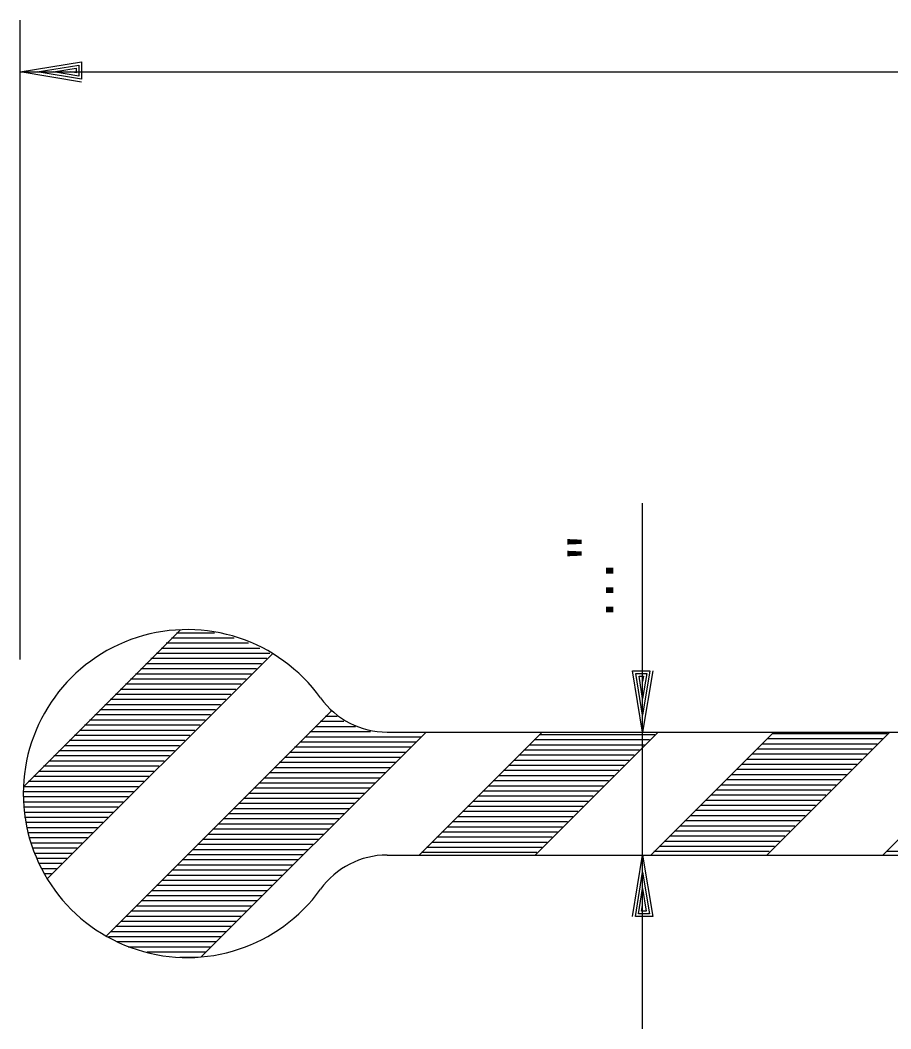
# Model space of a CAD drawing. Extents: x 44743.44 to 44747.1, y 44738.46 to 44741.29.
# Drawn here: x 44744.0225 to 44744.2437, y 44738.8171 to 44739.0734 of the extents above; entities that cross this region are included whole.
import ezdxf

# ---------------------------------------------------------------- set-up
doc = ezdxf.new("R2010")
doc.units = 0
for name, color, linetype in [('Level 1', 7, 'Continuous'), ('Level 10', 7, 'Continuous'), ('Level 8', 7, 'Continuous'), ('S-ANNO-TEXT', 7, 'Continuous')]:
    doc.layers.add(name, color=color, linetype=linetype)

msp = doc.modelspace()

# ---------------------------------------------------------------- linework, layer by layer
at = {"layer": 'Level 1'}
for p, q in [((44744.022493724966, 44738.91099515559), (44744.022493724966, 44739.07343265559)), ((44744.022493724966, 44739.060286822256), (44744.77199372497, 44739.060286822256)), ((44744.022493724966, 44739.060286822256), (44744.022493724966, 44739.060286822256)), ((44744.026827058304, 44739.060286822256), (44744.026827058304, 44739.060286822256)), ((44744.180629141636, 44738.89252640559), (44744.180629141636, 44738.95066182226)), ((44744.180629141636, 44738.896859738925), (44744.180629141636, 44738.896859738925)), ((44744.180629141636, 44738.86127640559), (44744.180629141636, 44738.89252640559)), ((44744.180629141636, 44738.89252640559), (44744.180629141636, 44738.89252640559)), ((44744.180629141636, 44738.81712015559), (44744.180629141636, 44738.86127640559)), ((44744.180629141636, 44738.86127640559), (44744.180629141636, 44738.86127640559)), ((44744.180629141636, 44738.85694307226), (44744.180629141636, 44738.85694307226))]:
    msp.add_line(p, q, dxfattribs=at)
for points in [[(44744.0380770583, 44739.05770348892), (44744.022493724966, 44739.060286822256), (44744.0380770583, 44739.06287015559), (44744.0380770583, 44739.05845348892), (44744.026827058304, 44739.060286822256), (44744.03741039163, 44739.06203682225), (44744.03741039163, 44739.05920348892), (44744.03099372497, 44739.060286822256), (44744.036743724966, 44739.06120348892), (44744.036743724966, 44739.06003682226), (44744.0353270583, 44739.060286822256)], [(44744.0622020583, 44738.917786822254), (44744.07187914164, 44738.917786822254)], [(44744.18321247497, 44738.90810973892), (44744.180629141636, 44738.89252640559), (44744.1780458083, 44738.90810973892), (44744.182462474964, 44738.90810973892), (44744.180629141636, 44738.896859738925), (44744.17887914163, 44738.907443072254), (44744.181712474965, 44738.907443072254), (44744.180629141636, 44738.90102640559), (44744.179712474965, 44738.90677640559), (44744.18087914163, 44738.90677640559), (44744.180629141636, 44738.90535973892)], [(44744.10130622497, 44738.89787015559), (44744.10144164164, 44738.89787015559)], [(44744.15437914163, 44738.89192223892), (44744.183712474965, 44738.89192223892)], [(44744.21366039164, 44738.89218265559), (44744.2428583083, 44738.89218265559)], [(44744.1780458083, 44738.84569307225), (44744.180629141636, 44738.86127640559), (44744.18321247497, 44738.84569307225), (44744.1787958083, 44738.84569307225), (44744.180629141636, 44738.85694307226), (44744.18237914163, 44738.84635973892), (44744.1795458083, 44738.84635973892), (44744.180629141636, 44738.85277640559), (44744.1815458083, 44738.84702640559), (44744.18037914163, 44738.84702640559), (44744.180629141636, 44738.84844307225)], [(44744.028743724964, 44738.85658890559), (44744.0304520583, 44738.85658890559)], [(44744.06302497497, 44738.83537015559), (44744.06775414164, 44738.83537015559)]]:
    msp.add_lwpolyline(points, dxfattribs=at)
at = {"layer": 'Level 10'}
for p, q in [((44744.115712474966, 44738.89252640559), (44744.32334789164, 44738.89252640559)), ((44744.115712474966, 44738.86127640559), (44744.32334789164, 44738.86127640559))]:
    msp.add_line(p, q, dxfattribs=at)
for centre, radius, start, end in [((44744.0649520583, 44738.87690140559), 0.04166666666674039, 35.68088333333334, 324.3147472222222), ((44744.115716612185, 44738.91335973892), 0.020833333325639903, 215.6853361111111, 270), ((44744.115716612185, 44738.84044307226), 0.020833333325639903, 90, 144.3146638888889)]:
    msp.add_arc(centre, radius, start, end, dxfattribs=at)
at = {"layer": 'Level 8'}
for points in [[(44744.02331664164, 44738.87862015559), (44744.0632333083, 44738.91853682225)], [(44744.06089997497, 44738.91648473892), (44744.076879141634, 44738.91648473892)], [(44744.058306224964, 44738.913880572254), (44744.08333747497, 44738.913880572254)], [(44744.05959789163, 44738.91518265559), (44744.080472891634, 44738.91518265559)], [(44744.029368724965, 44738.85521390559), (44744.0866395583, 44738.912484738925)], [(44744.0557020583, 44738.91127640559), (44744.08512914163, 44738.91127640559)], [(44744.057004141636, 44738.91257848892), (44744.085941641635, 44738.91257848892)], [(44744.053118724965, 44738.90867223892), (44744.08252497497, 44738.90867223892)], [(44744.0544208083, 44738.909974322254), (44744.083827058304, 44738.909974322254)], [(44744.05052497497, 44738.906068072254), (44744.079920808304, 44738.906068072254)], [(44744.0518270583, 44738.90737015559), (44744.08122289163, 44738.90737015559)], [(44744.047931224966, 44738.90346390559), (44744.07731664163, 44738.90346390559)], [(44744.049222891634, 44738.90476598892), (44744.07861872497, 44738.90476598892)], [(44744.04662914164, 44738.902161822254), (44744.076014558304, 44738.902161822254)], [(44744.044035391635, 44738.89955765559), (44744.07341039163, 44738.89955765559)], [(44744.0453270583, 44738.90085973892), (44744.07471247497, 44738.90085973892)], [(44744.04143122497, 44738.89695348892), (44744.07080622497, 44738.89695348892)], [(44744.0427333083, 44738.898255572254), (44744.072108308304, 44738.898255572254)], [(44744.04431664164, 44738.840703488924), (44744.10162914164, 44738.89800557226)], [(44744.100004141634, 44738.896568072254), (44744.1029833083, 44738.896568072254)], [(44744.03883747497, 44738.894349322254), (44744.068202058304, 44738.894349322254)], [(44744.0401395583, 44738.89565140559), (44744.06950414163, 44738.89565140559)], [(44744.09739997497, 44738.89396390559), (44744.10768122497, 44738.89396390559)], [(44744.0987020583, 44738.895265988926), (44744.10469164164, 44738.895265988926)], [(44744.03624372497, 44738.89174515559), (44744.06559789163, 44738.89174515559)], [(44744.0375458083, 44738.89304723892), (44744.06689997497, 44738.89304723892)], [(44744.06846247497, 44738.83538057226), (44744.1256083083, 44738.89252640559)], [(44744.094806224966, 44738.891359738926), (44744.1243583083, 44738.891359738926)], [(44744.0961083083, 44738.892661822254), (44744.1115145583, 44738.892661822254)], [(44744.12381664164, 44738.86127640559), (44744.15506664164, 44738.89252640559)], [(44744.153285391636, 44738.86127640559), (44744.184535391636, 44738.89252640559)], [(44744.18274372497, 44738.86127640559), (44744.21399372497, 44738.89252640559)], [(44744.212202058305, 44738.86127640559), (44744.243462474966, 44738.89252640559)], [(44744.2123583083, 44738.89088057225), (44744.241556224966, 44738.89088057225)], [(44744.241670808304, 44738.86127640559), (44744.272920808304, 44738.89252640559)], [(44744.03364997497, 44738.88914098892), (44744.06299372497, 44738.88914098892)], [(44744.034941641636, 44738.890443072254), (44744.064295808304, 44738.890443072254)], [(44744.0922020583, 44738.888755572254), (44744.12175414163, 44738.888755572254)], [(44744.09350414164, 44738.89005765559), (44744.12305622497, 44738.89005765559)], [(44744.15178539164, 44738.88931807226), (44744.1811083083, 44738.88931807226)], [(44744.153087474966, 44738.89062015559), (44744.18241039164, 44738.89062015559)], [(44744.2097333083, 44738.88827640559), (44744.23894164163, 44738.88827640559)], [(44744.211045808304, 44738.889578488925), (44744.24024372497, 44738.889578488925)], [(44744.031045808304, 44738.886536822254), (44744.060389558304, 44738.886536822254)], [(44744.03234789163, 44738.88783890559), (44744.06169164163, 44738.88783890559)], [(44744.0896083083, 44738.88615140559), (44744.1191395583, 44738.88615140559)], [(44744.090910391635, 44738.887453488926), (44744.12044164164, 44738.887453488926)], [(44744.149181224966, 44738.88671390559), (44744.17850414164, 44738.88671390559)], [(44744.1504833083, 44738.88801598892), (44744.179806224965, 44738.88801598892)], [(44744.20711872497, 44738.885672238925), (44744.2363270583, 44738.885672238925)], [(44744.2084208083, 44738.88697432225), (44744.2376395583, 44738.88697432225)], [(44744.0284520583, 44738.88393265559), (44744.05778539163, 44738.88393265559)], [(44744.02975414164, 44738.88523473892), (44744.05908747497, 44738.88523473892)], [(44744.0870145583, 44738.883547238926), (44744.11653539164, 44738.883547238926)], [(44744.08830622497, 44738.884849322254), (44744.117837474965, 44738.884849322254)], [(44744.1465770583, 44738.88410973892), (44744.175899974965, 44738.88410973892)], [(44744.14787914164, 44738.88541182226), (44744.1772020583, 44738.88541182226)], [(44744.20449372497, 44738.88306807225), (44744.23371247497, 44738.88306807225)], [(44744.20580622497, 44738.88437015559), (44744.235024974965, 44738.88437015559)], [(44744.0258583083, 44738.88132848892), (44744.05518122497, 44738.88132848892)], [(44744.027149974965, 44738.882630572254), (44744.056483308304, 44738.882630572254)], [(44744.0844208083, 44738.880943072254), (44744.113920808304, 44738.880943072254)], [(44744.08571247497, 44738.88224515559), (44744.11522289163, 44738.88224515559)], [(44744.14397289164, 44738.88150557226), (44744.1732958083, 44738.88150557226)], [(44744.145274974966, 44738.88280765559), (44744.17459789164, 44738.88280765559)], [(44744.201868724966, 44738.88046390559), (44744.231097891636, 44738.88046390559)], [(44744.20318122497, 44738.881765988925), (44744.23241039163, 44738.881765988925)], [(44744.02328539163, 44738.878724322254), (44744.052587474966, 44738.878724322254)], [(44744.02455622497, 44738.88002640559), (44744.0538895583, 44738.88002640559)], [(44744.081827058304, 44738.87833890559), (44744.11131664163, 44738.87833890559)], [(44744.08311872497, 44738.879640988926), (44744.11261872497, 44738.879640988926)], [(44744.141368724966, 44738.87890140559), (44744.17069164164, 44738.87890140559)], [(44744.1426708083, 44738.88020348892), (44744.171993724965, 44738.88020348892)], [(44744.199243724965, 44738.877859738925), (44744.2284833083, 44738.877859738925)], [(44744.20055622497, 44738.87916182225), (44744.2297958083, 44738.87916182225)], [(44744.02328539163, 44738.87742223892), (44744.05128539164, 44738.87742223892)], [(44744.02328539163, 44738.87612015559), (44744.0499833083, 44738.87612015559)], [(44744.07922289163, 44738.875734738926), (44744.1087020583, 44738.875734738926)], [(44744.08052497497, 44738.877036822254), (44744.110004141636, 44738.877036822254)], [(44744.1387645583, 44738.87629723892), (44744.168087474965, 44738.87629723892)], [(44744.14006664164, 44738.87759932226), (44744.1693895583, 44738.87759932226)], [(44744.19793122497, 44738.87655765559), (44744.22718122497, 44738.87655765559)], [(44744.023347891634, 44738.874818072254), (44744.048681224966, 44738.874818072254)], [(44744.02341039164, 44738.87351598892), (44744.04737914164, 44738.87351598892)], [(44744.07662914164, 44738.873130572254), (44744.10608747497, 44738.873130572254)], [(44744.077920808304, 44738.87443265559), (44744.10739997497, 44738.87443265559)], [(44744.13616039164, 44738.87369307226), (44744.1654833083, 44738.87369307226)], [(44744.137462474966, 44738.87499515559), (44744.16678539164, 44738.87499515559)], [(44744.19530622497, 44738.873953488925), (44744.224566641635, 44738.873953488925)], [(44744.19661872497, 44738.87525557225), (44744.22586872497, 44738.87525557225)], [(44744.02347289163, 44738.87221390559), (44744.0460770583, 44738.87221390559)], [(44744.023556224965, 44738.870911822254), (44744.044774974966, 44738.870911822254)], [(44744.074024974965, 44738.87052640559), (44744.1034833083, 44738.87052640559)], [(44744.0753270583, 44738.871828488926), (44744.10478539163, 44738.871828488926)], [(44744.133556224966, 44738.87108890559), (44744.16287914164, 44738.87108890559)], [(44744.1348583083, 44738.87239098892), (44744.164181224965, 44738.87239098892)], [(44744.192681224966, 44738.87134932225), (44744.2219520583, 44738.87134932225)], [(44744.19399372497, 44738.87265140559), (44744.22325414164, 44738.87265140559)], [(44744.0238895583, 44738.86960973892), (44744.04347289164, 44738.86960973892)], [(44744.0242333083, 44738.86830765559), (44744.0421708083, 44738.86830765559)], [(44744.07143122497, 44738.867922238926), (44744.10086872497, 44738.867922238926)], [(44744.0727333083, 44738.869224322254), (44744.10218122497, 44738.869224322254)], [(44744.1309520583, 44738.86848473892), (44744.160274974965, 44738.86848473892)], [(44744.13225414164, 44738.86978682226), (44744.1615770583, 44738.86978682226)], [(44744.190056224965, 44738.86874515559), (44744.21933747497, 44738.86874515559)], [(44744.19136872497, 44738.870047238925), (44744.22064997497, 44738.870047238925)], [(44744.02456664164, 44738.867005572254), (44744.040868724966, 44738.867005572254)], [(44744.02489997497, 44738.86570348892), (44744.03956664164, 44738.86570348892)], [(44744.0688270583, 44738.865318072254), (44744.0982645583, 44738.865318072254)], [(44744.07012914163, 44738.86662015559), (44744.099566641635, 44738.86662015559)], [(44744.12834789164, 44738.86588057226), (44744.1576708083, 44738.86588057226)], [(44744.129649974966, 44738.86718265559), (44744.15896247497, 44738.86718265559)], [(44744.18743122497, 44738.866140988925), (44744.21672289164, 44738.866140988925)], [(44744.18874372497, 44738.86744307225), (44744.218035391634, 44738.86744307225)], [(44744.025233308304, 44738.86440140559), (44744.0382645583, 44738.86440140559)], [(44744.02562914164, 44738.863099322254), (44744.036962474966, 44738.863099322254)], [(44744.0662333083, 44738.86271390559), (44744.09564997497, 44738.86271390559)], [(44744.06753539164, 44738.864015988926), (44744.09696247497, 44738.864015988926)], [(44744.125743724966, 44738.86327640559), (44744.15506664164, 44738.86327640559)], [(44744.1270458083, 44738.86457848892), (44744.156368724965, 44738.86457848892)], [(44744.18480622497, 44738.86353682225), (44744.214108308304, 44738.86353682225)], [(44744.18611872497, 44738.86483890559), (44744.2154208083, 44738.86483890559)], [(44744.02603539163, 44738.86179723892), (44744.03566039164, 44738.86179723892)], [(44744.026629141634, 44738.86049515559), (44744.0343583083, 44738.86049515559)], [(44744.06362914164, 44738.860109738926), (44744.0930458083, 44738.860109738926)], [(44744.064931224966, 44738.861411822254), (44744.09434789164, 44738.861411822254)], [(44744.12444164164, 44738.86197432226), (44744.1537645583, 44738.86197432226)], [(44744.183493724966, 44738.862234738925), (44744.21281664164, 44738.862234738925)], [(44744.242597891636, 44738.86230765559), (44744.27189997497, 44738.86230765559)], [(44744.02730622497, 44738.859193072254), (44744.033056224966, 44738.859193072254)], [(44744.0280145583, 44738.85789098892), (44744.03175414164, 44738.85789098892)], [(44744.061035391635, 44738.857505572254), (44744.09043122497, 44738.857505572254)], [(44744.06233747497, 44738.85880765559), (44744.0917333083, 44738.85880765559)], [(44744.05844164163, 44738.85490140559), (44744.0878270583, 44738.85490140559)], [(44744.0597333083, 44738.856203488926), (44744.089129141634, 44738.856203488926)], [(44744.05583747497, 44738.852297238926), (44744.085212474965, 44738.852297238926)], [(44744.0571395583, 44738.853599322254), (44744.0865145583, 44738.853599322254)], [(44744.05324372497, 44738.849693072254), (44744.08261872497, 44738.849693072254)], [(44744.05453539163, 44738.85099515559), (44744.0839208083, 44738.85099515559)], [(44744.0506395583, 44738.84708890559), (44744.08000414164, 44738.84708890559)], [(44744.051941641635, 44738.848390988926), (44744.081306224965, 44738.848390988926)], [(44744.04933747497, 44738.845786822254), (44744.0787020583, 44738.845786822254)], [(44744.04674372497, 44738.84318265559), (44744.07608747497, 44738.84318265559)], [(44744.048045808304, 44738.844484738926), (44744.077389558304, 44738.844484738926)], [(44744.0449208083, 44738.840578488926), (44744.073483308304, 44738.840578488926)], [(44744.04544164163, 44738.841880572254), (44744.07478539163, 44738.841880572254)], [(44744.04694164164, 44738.83927640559), (44744.0721708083, 44738.83927640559)], [(44744.04993122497, 44738.837974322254), (44744.070868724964, 44738.837974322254)], [(44744.05474372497, 44738.836672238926), (44744.069566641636, 44738.836672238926)]]:
    msp.add_lwpolyline(points, dxfattribs=at)

# ---------------------------------------------------------------- texts
at = {"layer": 'S-ANNO-TEXT'}
msp.add_text("…''", height=0.011666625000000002, rotation=90, dxfattribs=at).set_placement((44744.173149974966, 44738.92080765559))

doc.saveas('drawing.dxf')
